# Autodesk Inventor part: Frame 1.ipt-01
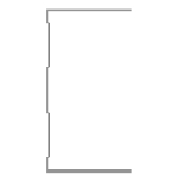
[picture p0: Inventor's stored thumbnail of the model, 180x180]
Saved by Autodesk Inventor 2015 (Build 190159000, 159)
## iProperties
IsCustomPart: 1
Created: 2015-04
Part Number: Frame 1.ipt-01
Material: Aluminum 6061
Description: Kévin Novo
Document SubType Name: Modeling
Standard: Kevin
Designer: suporte
Standards Organization: Kevin
Language: en-US
Size Designation: (Unnamed 1)
Categories: <MemberInstance><Categories><Category DisplayName="Structural Shapes" InternalName="089c4875-fa83-4c05-b084-43b9cc11f5ed" Mnemonic="GRDR"><CategoryParameter Dis
Density: 2.7 g/cm^3
Appearance: Aluminum - Flat
_CCFamilyMember: 1
_CCFamilyDisplayName: Kévin - Kévin Novo
_FrameMemberDoc: Frame Member File
_Version: 15.0.0
_GetPNFromCC: 1
G_L: 1000,000 mm
G_W: 50,000 mm
G_H: 75,000 mm
+C9D39AE0-1326-43E3-B6E5-C893CB557A5B+CUTDETAIL1: Cut
+49A0EB86-DFA6-40D8-9207-D27EBB6706F4+CUTDETAIL2: Cut
Author: suporte
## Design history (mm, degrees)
node "Start Plane"
node "End Plane"
sketch "Sketch"
  geometry: L1 (24.7, 37.5)-(24.7, 36.9); L2 (24.7, 36.9)-(-24.7, 36.9); L3 (-24.7, -36.9)-(24.7, -36.9); L4 (24.7, -36.9)-(24.7, -37.5); L5 (24.7, -37.5)-(-25.3, -37.5); L6 (-25.3, 37.5)-(24.7, 37.5); L7 (-24.7, 36.9)-(-24.7, 31.9); L8 (-24.7, 31.9)-(-23.3, 30.5); L9 (-23.3, 30.5)-(-23.3, 10.934); L10 (-23.3, 10.934)-(-24.7, 9.534); L11 (-24.7, 9.534)-(-24.7, -9.534); L12 (-24.7, -9.534)-(-23.3, -10.934); L13 (-23.3, -10.934)-(-23.3, -30.5); L14 (-23.3, -30.5)-(-24.7, -31.9); L15 (-24.7, -31.9)-(-24.7, -36.9); L16 (-25.3, -37.5)-(-25.3, -31.651); L17 (-25.3, -31.651)-(-23.9, -30.251); L18 (-23.9, -30.251)-(-23.9, -11.183); L19 (-23.9, -11.183)-(-25.3, -9.783); L20 (-25.3, -9.783)-(-25.3, 9.783); L21 (-25.3, 9.783)-(-23.9, 11.183); L22 (-23.9, 11.183)-(-23.9, 30.251); L23 (-23.9, 30.251)-(-25.3, 31.651); L24 (-25.3, 31.651)-(-25.3, 37.5); L25 (-25.3, 0)-(30.37, 0); 3 further points
  constraints: 50 end point, 10 point on line, 9 parallel, 5 perpendicular, 4 equal length, 3 midpoint, 3 vertical, 2 vertical alignment, 1 collinear, 1 horizontal, 1 horizontal alignment
  dimensions: "d3" = 0.6 distance of L1.start L1.end (= d6); "d5" = 75 distance between parallel lines of L5 L6; "d6" = 0.6 distance between parallel lines of L24 L7 (= d8); "d7" = 0.6 distance between parallel lines of L8 L23 (= d8); "d8" = 0.6 distance between parallel lines of L22 L9 (= d12); "Espessura" = 0.6 distance between parallel lines of L17 L14; "d10" = 0.6 distance between parallel lines of L13 L18 (= Espessura); "d11" = 0.6 distance between parallel lines of L12 L19 (= Espessura); "d12" = 0.6 distance between parallel lines of L21 L10 (= d11); "d13" = 5 distance of L2.end L7.end; "d15" = 135 deg angle of L9 L8; "d16" = 2 distance between parallel lines of L24 L9; "d17" = 50 distance of L6.start L1.start
extrude "Body" join sketch "Sketch" stored distance "d24" = 0.13; taper "d25" = 0 deg
node "Driven Length"
  sketch "Sketch10"
    geometry: L1 (0, 0)-(10, 0) reference
    constraints: 2 end point, 1 horizontal
  workplane "Work Plane7"
  sketch "Sketch11"
    geometry: L1 (-2, -12.5)-(12, -12.5) reference; L2 (-2, 987.5)-(12, 987.5) reference
    dimensions: "d27" = 1000 distance between parallel lines of L1 L2 (derived)
workplane "Work Plane8"
split "Split1"
workplane "Work Plane9"
split "Split2"
body "Solid1"
other parameters: "G_OFFSET_START" = 12.5 [user parameter; used in 1 equation term], "G_OFFSET_END" = -12.5 [user parameter; used in 1 equation term], "d22" = -12.5 (= -G_OFFSET_START), "d23" = 987.5 (= tamanho + G_OFFSET_END), "G_L" = 1000 (= d27) [user parameter], "d34" = 90 deg
